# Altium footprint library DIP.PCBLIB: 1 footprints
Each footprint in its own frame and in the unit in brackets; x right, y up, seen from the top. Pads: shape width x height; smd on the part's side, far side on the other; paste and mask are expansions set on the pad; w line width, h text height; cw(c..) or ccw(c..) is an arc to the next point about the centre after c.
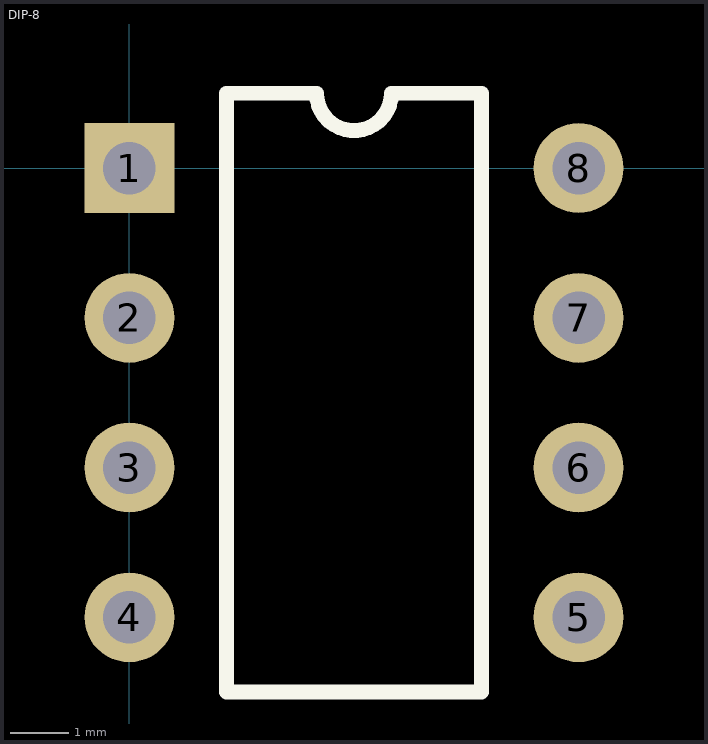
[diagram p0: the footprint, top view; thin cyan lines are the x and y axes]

## DIP-8 [mil]
pads (8):
  rect 60x60 hole 35: 1(0,0)
  round 60 hole 35: 2(0,-100) 3(0,-200) 4(0,-300) 5(300,-300) 6(300,-200) 7(300,-100) 8(300,0)
Top Overlay:
  lines w10: 65,-350 235,-350 235,50 175,50 cw(c150,50) 125,50 65,50 65,-350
